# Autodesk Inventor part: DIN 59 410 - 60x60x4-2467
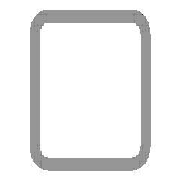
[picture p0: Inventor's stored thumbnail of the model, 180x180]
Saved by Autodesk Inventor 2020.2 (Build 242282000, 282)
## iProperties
Manager: www.cadconsulting.pl
Company: Fabian Stasiak CAD Consulting
IsCustomPart: 1
_CCFamilyMember: 60
_CCFamilyDisplayName: DIN 59410 (Kwadrat) - Rurki stalowe o przekroju kwadratowym formowane na gorąco
_FrameMemberDoc: Frame Member File
_Version: 15.0.0
_GetPNFromCC: 1
Created: 2015-01
Part Number: DIN 59 410 - 60x60x4-2467
Material: Stal, miękka
Description: Rurki stalowe o przekroju kwadratowym formowane na gorąco
Document SubType Name: Modellieren
Standard: DIN
Designer: F.Stasiak
Standards Organization: DIN
Language: pl-PL
Size Designation: 60x60x4
Categories: <MemberInstance><Categories><Category DisplayName="Kształtowniki konstrukcyjne" InternalName="089c4875-fa83-4c05-b084-43b9cc11f5ed" Mnemonic="GRDR"><CategoryPar
Stock Number: 60x60x4
Density: 7.85 g/cm^3
Appearance: Częściowo polerowana
Mass: 23928.9 g
Surface Area: 12217.8 cm^2
Volume: 3048.27 cm^3
Catalog Web Link: www.expertbooks.pl
G_L: 2467,000 mm
G_W: 60,000 mm
G_H: 60,000 mm
+2514B748-BDEE-4240-A553-66AAD497649D+CUTDETAIL1: Wytnij
Author: F.Stasiak
Subject: Zbiór ćwiczeń. Autodesk Inventor 2020. Kurs Professional
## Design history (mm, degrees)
node "Płaszczyzna początkowa"
node "Płaszczyzna końcowa"
sketch "Szkic1"
  geometry: L1 (-22, 30)-(22, 30); L2 (30, 22)-(30, -22); L3 (22, -30)-(-22, -30); L4 (-30, -22)-(-30, 22); L5 (-51.899, 0)-(51.899, 0) reference; L6 (0, -51.899)-(0, 51.899) reference; L7 (-22, 26)-(22, 26); L8 (26, 22)-(26, -22); L9 (22, -26)-(-22, -26); L10 (-26, -22)-(-26, 22); A1 r 8 centre (-22, 22) between (-22, 30) and (-30, 22); A2 r 8 centre (22, 22) between (30, 22) and (22, 30); A3 r 8 centre (22, -22) between (22, -30) and (30, -22); A4 r 8 centre (-22, -22) between (-30, -22) and (-22, -30); A5 r 4 centre (-22, 22) between (-22, 26) and (-26, 22); A6 r 4 centre (22, 22) between (26, 22) and (22, 26); A7 r 4 centre (22, -22) between (22, -26) and (26, -22); A8 r 4 centre (-22, -22) between (-26, -22) and (-22, -26); 3 further points
  constraints: 16 end point, 16 point on circle, 8 centre point, 8 tangent, 6 point on line, 4 parallel, 3 equal radius, 3 perpendicular, 1 horizontal, 7 other
  dimensions: "b" = 60 distance of point (-30, 30) point (30, 30); "msp_r" = 8 radius of A1 (= 2 x ParT); "d8" = 30 distance between parallel lines of L4 L6 (= d9); "d9" = 30 distance between parallel lines of L3 L5 (= 0.5 x b); "d10" = 4 distance between parallel lines of L3 L9 (= ParT)
extrude "Bryła" new body sketch "Szkic1" taper "d4" = 0 deg; stored distance "NLG" = 10
node "Driven Length"
  sketch "Sketch2"
    geometry: L1 (0, 0)-(10, 0) reference
    constraints: 2 end point, 1 horizontal
  workplane "Work Plane3"
  sketch "Sketch3"
    geometry: L1 (-2, 33)-(12, 33) reference; L2 (-2, 2500)-(12, 2500) reference
    dimensions: "d14" = 2467 distance between parallel lines of L1 L2 (derived)
node "Płaszczyzna konstrukcyjna4"
feature "Podział1"
body "Solid1"
other parameters: "ParT" = 4, "G_OFFSET_START" = -33 [user parameter; used in 1 equation term], "G_OFFSET_END" = 0 [user parameter; used in 1 equation term], "d11" = 33 (= -G_OFFSET_START), "G_L" = 2467 (= d14) [user parameter], "d13" = 90 deg
